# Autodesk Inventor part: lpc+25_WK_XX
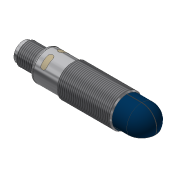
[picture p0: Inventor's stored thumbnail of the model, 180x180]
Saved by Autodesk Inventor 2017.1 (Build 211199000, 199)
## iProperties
Shininess: 20.0
Length Units: 11269
Angle Units: 11279
Time Units: 11290
Mass Units: 11283
Length Display Precision: 2
Angle Display Precision: 2
Part Number: lpc+25_WK_XX
Material: Nichtrostender Stahl - 440C
Document SubType Name: Modellieren
Description: Ipc-25 /CXX/M18
Checked By: Alves
Created: 2005-08
Designer: Ohle
Manufacturer: Standard
Standards Organization: Custom
Appearance: Aluminium - poliert
Density: 0.0
Volumn: 0.0
Area: 0.0
PropertySet Name: Model Information
Control State: 0
Master: False
Checked Out: False
BESTELLNUMMER: Ipc-25 /CXX/M18
ME: ST
Title: Ipc Sensoren
Author: Ohle
Comments: keine Bemerkung
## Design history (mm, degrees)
sketch "Skizze10"
  geometry: L1 (-43.018, 0)-(22.982, 0); L2 (-39.018, 6.5)-(-39.018, 7.25); L3 (-45.9, 8)-(-45.9, 8); L4 (-23.268, 9)-(5.732, 9); L5 (1.482, 0)-(-82.2, 0); L6 (-24.018, 8.25)-(-23.268, 9); L7 (6.482, 8.25)-(5.732, 9); L8 (-50.518, 6)-(-39.518, 6); L9 (-37.418, 8.25)-(-24.018, 8.25); L10 (-51.018, 4.5)-(-43.018, 4.5); L11 (-43.018, 0)-(-43.018, 4.5); L12 (-37.518, 8.25)-(-38.018, 8.25); L13 (-39.518, 6)-(-39.018, 6.5); L14 (-51.018, 5.5)-(-51.018, 4.5); L15 (-51.018, 5.5)-(-50.518, 6); L16 (-37.518, 8.25)-(-37.518, 8.15); L17 (-37.518, 8.15)-(-37.418, 8.15); L18 (-37.418, 8.15)-(-37.418, 8.25); L19 (6.482, 8.25)-(14.732, 8.25); L20 (22.982, 0)-(22.982, 0); A1 r 1 centre (-38.018, 7.25) between (-38.018, 8.25) and (-39.018, 7.25); A2 r 8.25 centre (14.732, 0) between (22.982, 0) and (14.732, 8.25); 4 further points
  constraints: 41 end point, 8 point on line, 5 parallel, 4 perpendicular, 4 point on circle, 4 tangent, 2 centre point, 2 horizontal, 1 collinear
  dimensions: "d171" = 4.5 distance between parallel lines of L10 L1; "d250" = 0.75 distance from line of L7.start L4; "d256" = 45 deg angle of L4 L6; "d257" = 8.25 distance between parallel lines of L5 L9; "d263" = 8.25 distance between parallel lines of L5 L12; "d266" = 12 distance from line of L2 L14.start; "d269" = 6 distance between parallel lines of L5 L8; "d289" = 135 deg angle of L7 L4; "d290" = 0.5 horizontal distance of L8.end L2.start; "d291" = 45 deg angle of L13 L8 (derived); "d293" = 0.5 horizontal distance of L14.start L8.start; "d294" = 45 deg angle of L15 L8 (derived); "d295" = 8 distance of L10.start L10.end; "d296" = 1.5 distance of L12.start point (-39.018, 8.25); "d297" = 0.1 distance of L16.end L17.end; "d298" = 8.15 distance between parallel lines of L17 L1; "d299" = 15 distance from line of L6.start L2; "d300" = 1 radius of A1; "d338" = 8.25 radius of A2; "d339" = 16.5 horizontal distance of L20.end L7.start; "d340" = 8.25 distance between parallel lines of L1 L19 (derived); "d365" = 30.5 distance of L7.start L6.start
revolve "Grundkörper" sketch "Skizze10" stored, may be unused: angle "d168" = 90 deg
feature "Gewinde M12" dims "d174" = 10, "d175" = 0
feature "Gewinde M 18" dims "d179" = 10, "d180" = 0
workplane "Arbeitsebene1"
workplane "Arbeitsebene2"
sketch "Skizze13"
  geometry: L1 (-3.409, -3.409)-(3.61, 3.61); L2 (-3.439, 3.439)-(4.105, -4.105); L3 (-12.6, 0)-(12.6, 0) reference; C1 r 0.5 at (2.121, -2.121); C2 r 0.5 at (2.121, 2.121); C3 r 0.5 at (-2.121, 2.121); C4 r 0.5 at (-2.121, -2.121); C5 r 4.5 at (0, 0) reference; C6 r 0.5 at (0, 0); A1 r 3 centre (0, 0) between (-2.121, 2.121) and (2.121, 2.121); 2 further points
  constraints: 6 centre point, 6 point on line, 4 coincident, 4 end point, 4 equal radius, 4 point on circle, 1 horizontal alignment, 1 perpendicular
  dimensions: "d208" = 1 diameter of C3; "d209" = 6 diameter of A1
extrude "Pole" join sketch "Skizze13" distance "d212" = 7; taper "d213" = 0 deg
fillet "Rundung Pole" dims "d214" = 0.5
sketch "Skizze14"
  geometry: C1 r 0.5 at (0, -4.5); A1 r 4.5 centre (0, 0) between (4.435, -0.762) and (4.435, 0.762); A2 r 4.5 centre (0, 0) between (0, 4.5) and (0.499, 4.472) reference; A3 r 0.5 centre (0, 4.5) between (-0.499, 4.472) and (0.499, 4.472); 3 further points
  constraints: 9 point on circle, 3 centre point, 3 coincident, 1 horizontal alignment, 1 vertical alignment
  dimensions: "d215" = 9 diameter of A1; "d280" = 1 diameter of A3; "d330" = 1 diameter of C1
extrude "Verdrehsicherung" join sketch "Skizze14" distance "d217" = 7; taper "d218" = 0 deg
sketch "Skizze18"
  geometry: C1 r 7.25 at (0, 0) reference; C2 r 1 at (-8.15, 0)
  constraints: 1 centre point, 1 horizontal alignment
  dimensions: "d328" = 2 diameter of C2; "d329" = 8.15 distance of C1.centre C2.centre
extrude "Bohrung Ausrichtung" cut sketch "Skizze18" distance "d316" = 0.75; taper "d317" = 0 deg
workplane "Arbeitsebene4"
sketch "Skizze19"
  geometry: L1 (-39.018, 0)-(-30.18, 0); L2 (-34.718, -7.5)-(-34.718, -3); L3 (-31.718, -7.5)-(-31.718, -3); L4 (-31.718, 3)-(-31.718, 7.5); L5 (-34.718, 3)-(-34.718, 7.5); A1 r 1.5 centre (-33.218, 3) between (-31.718, 3) and (-34.718, 3); A2 r 1.5 centre (-33.218, -3) between (-34.718, -3) and (-31.718, -3); A3 r 1.5 centre (-33.218, 7.5) between (-31.718, 7.5) and (-34.718, 7.5); A4 r 1.5 centre (-33.218, -7.5) between (-34.718, -7.5) and (-31.718, -7.5); 4 further points; 1 other entity
  constraints: 10 end point, 8 point on circle, 8 tangent, 4 centre point, 3 equal radius, 2 vertical alignment, 1 horizontal, 2 other
  dimensions: "d319" = 3 diameter of A2; "d320" = 6 distance of A2.centre A1.centre; "d321" = 4.5 distance of A1.centre A3.centre; "d322" = 4.5 distance of A4.centre A2.centre; "d323" = 3 distance from line of A2.centre L1; "d324" = 5.8 dimension on A1.centre; "d325" = 5.8 dimension on A2.centre
feature "Prägen LED-Fenster" sketch "Skizze19" dims "d326" = 0.01, "d327" = 0
workplane "Arbeitsebene5"
sketch "Skizze20"
  geometry: L1 (14.732, -8.25)-(14.732, 8.25) reference; L2 (6.482, -8.25)-(6.482, 8.25) reference; L3 (14.732, -8.25)-(14.732, 8.25) reference; L4 (6.982, -8.25)-(24.008, -8.25); L5 (24.008, -8.25)-(24.008, 8.25); L6 (24.008, 8.25)-(6.982, 8.25); L7 (6.982, 8.25)-(6.982, -8.25)
  constraints: 8 end point, 2 parallel, 1 horizontal, 1 perpendicular
  dimensions: "d342" = 0.5 distance between parallel lines of L7 L2
extrude "USW-Fläche Winkelkopf" cut sketch "Skizze20" distance "d343" = 4.8; taper "d344" = 0 deg
sketch "Skizze21"
  geometry: C1 r 7 at (-14.732, 0); A1 r 7.494 centre (-14.732, 0) between (-14.732, 7.494) and (-14.732, -7.494) reference
  constraints: 1 centre point, 1 coincident
  dimensions: "d345" = 14 diameter of C1
extrude "Extrusion6" cut sketch "Skizze21" distance "d346" = 0.01; taper "d347" = 0 deg
sketch "Skizze22"
  geometry: C1 r 7 at (0, 0) reference; C2 r 4 at (0, 0)
  constraints: 1 centre point, 1 coincident
  dimensions: "d348" = 8 diameter of C2
extrude "Extrusion7" join sketch "Skizze22" distance "d349" = 0.01; taper "d350" = 0 deg
sketch "Skizze28"
  geometry: L1 (-6.482, 8.25)-(-14.732, 8.25) reference; L2 (-6.482, 8.25)-(-6.482, -8.25) reference; L3 (-14.732, -3.45)-(-22.226, -3.45) reference; L4 (-14.732, 8.15)-(-6.482, 8.15); A1 r 8.25 centre (-14.732, 0) between (-14.732, 8.25) and (-22.226, -3.45) reference; A2 r 8.15 centre (-14.732, 0) between (-14.732, 8.15) and (-22.116, -3.45)
  constraints: 2 end point, 2 point on circle, 2 point on line, 1 centre point, 1 coincident, 1 perpendicular, 1 tangent
  dimensions: "d362" = 0.1 radial gap between concentric circles of A2 A1
extrude "Extrusion8" cut sketch "Skizze28" stored distance "d363" = 0.3; taper "d364" = 0 deg
feature "Verdickung1" dims "d366" = 0.1, "d367" = 0.1
sketch "Skizze29"
  geometry: C1 r 5.5 at (0, 0); C2 r 4.5 at (0, 0); C3 r 4.15 at (0, 0); C4 r 5.25 at (0, 0); 2 further points
  constraints: 4 centre point
  dimensions: "d368" = 8.3 diameter of C3; "d369" = 10.5 diameter of C4
extrude "Extrusion9" join sketch "Skizze29" distance "d370" = 0.2; taper "d371" = 0 deg
sketch "Skizze30"
  geometry: C1 r 5.25 at (0, 0) reference; C2 r 7.996 at (0, 0); 1 further point
  constraints: 1 centre point
extrude "Extrusion10" cut sketch "Skizze30" distance "d372" = 1.8; taper "d373" = 0 deg
chamfer "Fase2" distance "d374" = 0.75; stored, may be unused: second distance "d375" = 2, angle "d376" = 30 deg
node "Volumenkörper1"
node "Volumenkörper"
node "Flächenkörper"
node "Projizierte Kontur2"
node "Projizierte Kontur3"
other parameters: "d10" = 14, "d73" = -35, "d130" = 0.2, "d207" = -95.5, "d318" = 8.25, "d341" = -8.25
